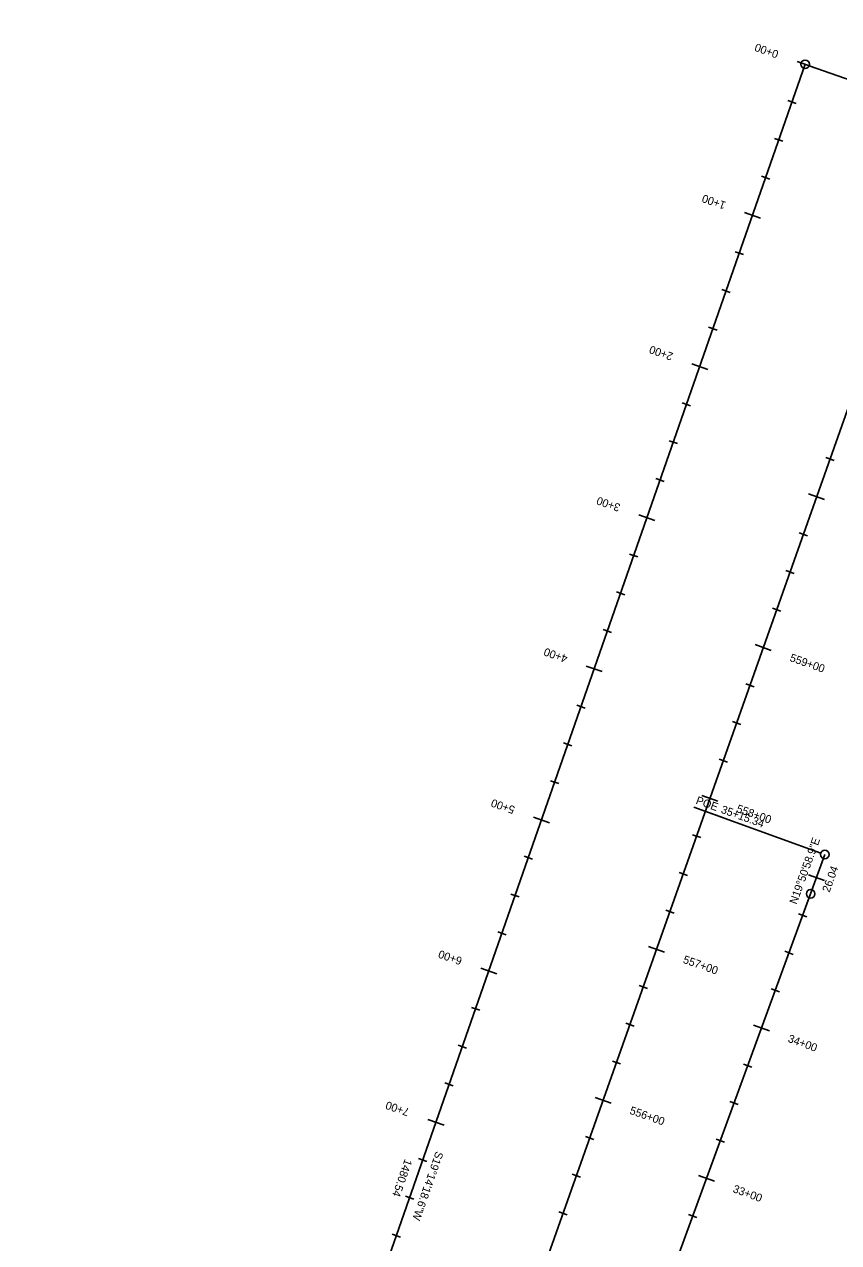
# Model space of a CAD drawing. Extents: x 2300830 to 2307917, y 756066 to 766359.
# Drawn here: x 2304398 to 2304907, y 764235 to 764996 of the extents above; entities that cross this region are included whole.
import ezdxf

# ---------------------------------------------------------------- set-up
doc = ezdxf.new("R2010")
doc.units = 0
for name, color, linetype in [('Default', 7, 'Continuous'), ('Draft_Bearing Label', 7, 'Continuous'), ('Draft_Station Cardinal Points', 7, 'Continuous'), ('Draft_Station Labels Major', 7, 'Continuous'), ('Draft_Station Ticks Major', 7, 'Continuous'), ('Draft_Station Ticks Minor', 7, 'Continuous'), ('Geom_Baseline', 7, 'Continuous')]:
    doc.layers.add(name, color=color, linetype=linetype)

msp = doc.modelspace()

# ---------------------------------------------------------------- linework, layer by layer
at = {"layer": 'Default'}
for p, q in [((2304441.78, 763425.01), (2305466.94, 766322.62)), ((2304886.16, 764971.52), (2304398.32, 763573.66)), ((2304705.33, 763950.07), (2304889.61, 764453.32))]:
    msp.add_line(p, q, dxfattribs=at)
at = {"layer": 'Draft_Station Cardinal Points'}
for p, q in [((2304886.16, 764971.52), (2304886.16, 764971.52)), ((2304888.68, 764970.64), (2304968.3, 764942.86)), ((2304895.94, 764478.72), (2304816.62, 764507.35)), ((2304816.62, 764507.35), (2304835.13, 764500.67)), ((2304898.45, 764477.81), (2304898.45, 764477.81)), ((2304889.61, 764453.32), (2304889.61, 764453.32))]:
    msp.add_line(p, q, dxfattribs=at)
for centre in [(2304886.16, 764971.52), (2304898.45, 764477.81), (2304889.61, 764453.32)]:
    msp.add_circle(centre, 2.67, dxfattribs=at)
at = {"layer": 'Draft_Station Ticks Major'}
for p, q in [((2304891.2, 764969.76), (2304881.17, 764973.26)), ((2304858.25, 764875.35), (2304848.22, 764878.85)), ((2304825.3, 764780.93), (2304815.27, 764784.43)), ((2304888.34, 764703.22), (2304898.35, 764699.68)), ((2304792.35, 764686.52), (2304782.32, 764690.02)), ((2304854.99, 764608.95), (2304865, 764605.4)), ((2304759.4, 764592.1), (2304749.37, 764595.6)), ((2304821.63, 764514.67), (2304831.64, 764511.13)), ((2304726.45, 764497.69), (2304716.42, 764501.19)), ((2304888.22, 764465.2), (2304898.21, 764461.59)), ((2304788.28, 764420.4), (2304798.29, 764416.86)), ((2304693.5, 764403.27), (2304683.47, 764406.77)), ((2304853.89, 764371.3), (2304863.86, 764367.65)), ((2304754.92, 764326.12), (2304764.94, 764322.58)), ((2304660.55, 764308.86), (2304650.52, 764312.36)), ((2304819.51, 764277.4), (2304829.48, 764273.75))]:
    msp.add_line(p, q, dxfattribs=at)
at = {"layer": 'Draft_Station Ticks Minor'}
for p, q in [((2304880.53, 764947.01), (2304875.32, 764948.83)), ((2304872.29, 764923.41), (2304867.08, 764925.23)), ((2304864.05, 764899.8), (2304858.84, 764901.62)), ((2304847.58, 764852.6), (2304842.37, 764854.41)), ((2304839.34, 764828.99), (2304834.13, 764830.81)), ((2304831.1, 764805.39), (2304825.89, 764807.21)), ((2304814.63, 764758.18), (2304809.42, 764760)), ((2304806.39, 764734.58), (2304801.18, 764736.39)), ((2304899.11, 764725.93), (2304904.31, 764724.09)), ((2304798.15, 764710.97), (2304792.94, 764712.79)), ((2304882.43, 764678.79), (2304887.64, 764676.95)), ((2304781.68, 764663.76), (2304776.47, 764665.58)), ((2304874.09, 764655.22), (2304879.3, 764653.38)), ((2304773.44, 764640.16), (2304768.23, 764641.98)), ((2304865.76, 764631.65), (2304870.96, 764629.81)), ((2304765.2, 764616.56), (2304759.99, 764618.38)), ((2304849.08, 764584.52), (2304854.28, 764582.68)), ((2304748.73, 764569.35), (2304743.52, 764571.17)), ((2304840.74, 764560.95), (2304845.95, 764559.11)), ((2304740.49, 764545.74), (2304735.28, 764547.56)), ((2304832.4, 764537.38), (2304837.61, 764535.54)), ((2304732.25, 764522.14), (2304727.04, 764523.96)), ((2304815.73, 764490.24), (2304820.93, 764488.4)), ((2304715.78, 764474.93), (2304710.57, 764476.75)), ((2304807.39, 764466.67), (2304812.59, 764464.83)), ((2304707.54, 764451.33), (2304702.33, 764453.15)), ((2304799.05, 764443.11), (2304804.25, 764441.26)), ((2304882.1, 764440.84), (2304887.29, 764438.95)), ((2304699.3, 764427.73), (2304694.09, 764429.54)), ((2304873.51, 764417.37), (2304878.69, 764415.47)), ((2304782.37, 764395.97), (2304787.58, 764394.13)), ((2304864.91, 764393.89), (2304870.09, 764391.99)), ((2304682.83, 764380.52), (2304677.62, 764382.34)), ((2304774.03, 764372.4), (2304779.24, 764370.56)), ((2304674.59, 764356.91), (2304669.38, 764358.73)), ((2304765.7, 764348.83), (2304770.9, 764346.99)), ((2304847.72, 764346.94), (2304852.9, 764345.04)), ((2304666.35, 764333.31), (2304661.14, 764335.13)), ((2304839.12, 764323.47), (2304844.3, 764321.57)), ((2304749.02, 764301.7), (2304754.22, 764299.85)), ((2304830.53, 764299.99), (2304835.71, 764298.09)), ((2304649.88, 764286.1), (2304644.67, 764287.92)), ((2304740.68, 764278.13), (2304745.88, 764276.29)), ((2304641.64, 764262.5), (2304636.43, 764264.32)), ((2304732.34, 764254.56), (2304737.55, 764252.72)), ((2304813.33, 764253.04), (2304818.52, 764251.14)), ((2304633.4, 764238.89), (2304628.19, 764240.71))]:
    msp.add_line(p, q, dxfattribs=at)
at = {"layer": 'Geom_Baseline'}
for p, q in [((2304441.78, 763425.01), (2305466.94, 766322.62)), ((2304886.16, 764971.52), (2304398.32, 763573.66)), ((2304889.61, 764453.32), (2304898.45, 764477.81)), ((2304705.33, 763950.07), (2304889.61, 764453.32))]:
    msp.add_line(p, q, dxfattribs=at)

# ---------------------------------------------------------------- texts
at = {"layer": 'Draft_Bearing Label'}
for s, rotation, p in [('N19°50\'58.9"E', 70.1503, (2304880.85, 764446.37)), ('26.04', 70.1503, (2304901.36, 764453.81)), ('S19°14\'18.6"W', 250.7615, (2304655.52, 764292.8)), ('1480.54', 250.7615, (2304636.07, 764287.93))]:
    msp.add_text(s, height=5, rotation=rotation, dxfattribs=at).set_placement(p)
at = {"layer": 'Draft_Station Cardinal Points'}
for s, p in [('POE ', (2304817.46, 764509.69)), ('35+15.34', (2304833.17, 764504.02))]:
    msp.add_text(s, height=5, rotation=340.1503, dxfattribs=at).set_placement(p)
at = {"layer": 'Draft_Station Labels Major'}
for s, rotation, p in [('0+00', 160.7615, (2304869.99, 764979.82)), ('1+00', 160.7615, (2304837.04, 764885.4)), ('2+00', 160.7615, (2304804.09, 764790.98)), ('3+00', 160.7615, (2304771.14, 764696.57)), ('4+00', 160.7615, (2304738.19, 764602.15)), ('559+00', 340.5164, (2304876.16, 764598.8)), ('5+00', 160.7615, (2304705.24, 764507.74)), ('558+00', 340.5164, (2304842.8, 764504.53)), ('6+00', 160.7615, (2304672.29, 764413.32)), ('557+00', 340.5164, (2304809.45, 764410.26)), ('34+00', 339.88822, (2304874.95, 764360.93)), ('7+00', 160.7615, (2304639.34, 764318.91)), ('556+00', 340.5164, (2304776.09, 764315.98)), ('33+00', 339.88822, (2304840.56, 764267.03))]:
    msp.add_text(s, height=5, rotation=rotation, dxfattribs=at).set_placement(p)

doc.saveas('drawing.dxf')
